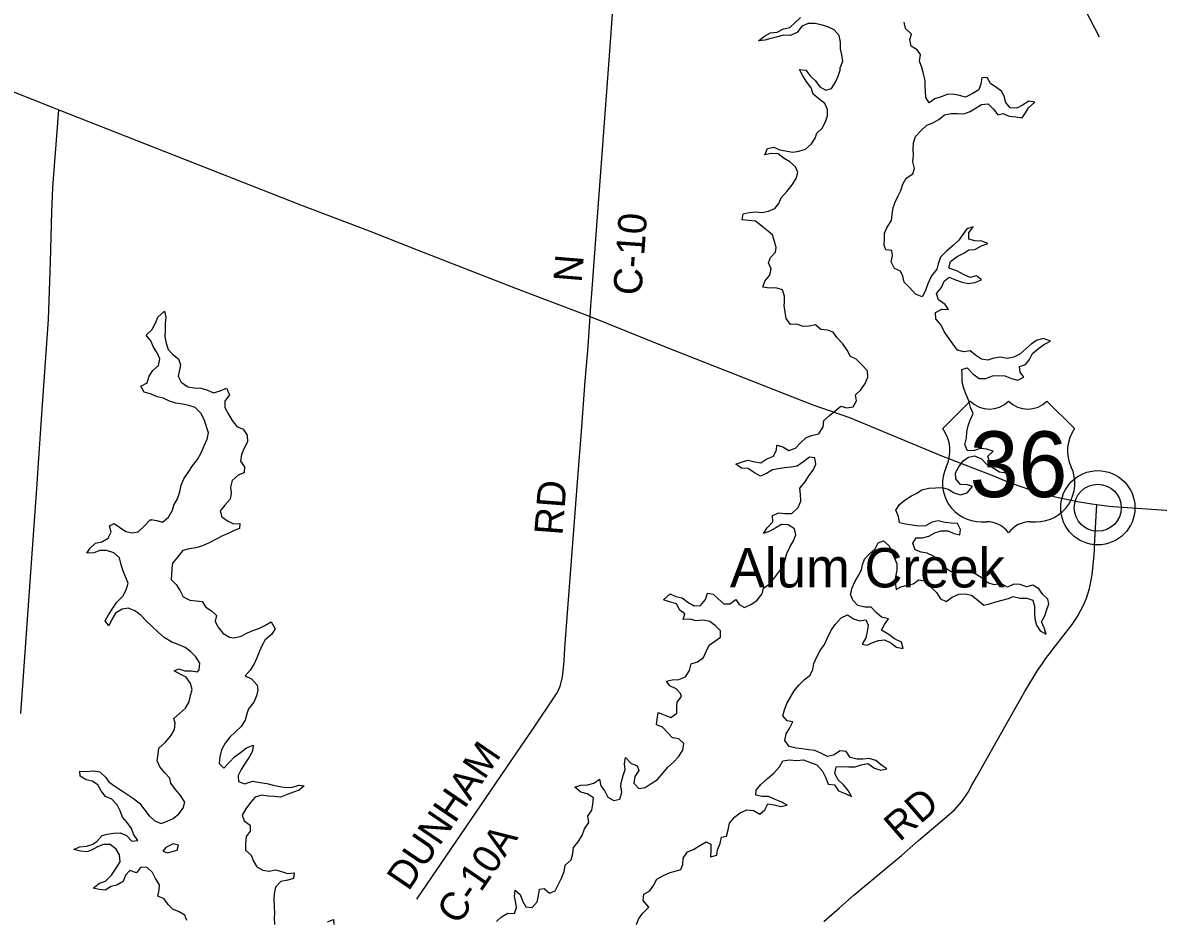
# Model space of a CAD drawing. Extents: x 1674899 to 2057726, y 653888 to 988278.
# Drawn here: x 1833082 to 1845104, y 821739 to 831243 of the extents above; entities that cross this region are included whole.
import ezdxf

# ---------------------------------------------------------------- set-up
doc = ezdxf.new("R2010")
doc.units = 0
for name, color, linetype in [('GM_X_County_Road', 7, 'Continuous'), ('GM_X_County_Road_Text', 7, 'Continuous'), ('GM_X_Major_Lake', 7, 'Continuous'), ('GM_X_Township_ROW', 7, 'Continuous'), ('GM_X_Unincorporated', 7, 'Continuous'), ('GM_X_Unincorporated_Location', 7, 'Continuous'), ('GM_X_Unincorporated_Text', 7, 'Continuous'), ('GM_X_US_Location', 7, 'Continuous'), ('GM_X_US_Route', 7, 'Continuous'), ('GM_X_US_Shield', 7, 'Continuous'), ('SH_Data', 7, 'Continuous')]:
    doc.layers.add(name, color=color, linetype=linetype)

msp = doc.modelspace()

# ---------------------------------------------------------------- linework, layer by layer
at = {"layer": 'GM_X_County_Road'}
for points in [[(1839090, 828131), (1839096, 828247), (1839106, 828377), (1839155, 829045), (1839297, 830940), (1839419, 832616), (1839427, 832761), (1839419, 832807), (1839405, 832831)], [(1833063, 823927), (1833158, 825274), (1833233, 826364), (1833244, 826526), (1833284, 827097), (1833354, 828099), (1833377, 828710), (1833389, 829242), (1833401, 829499), (1833463, 830322)], [(1837255, 821964), (1838352, 823573), (1838477, 823753), (1838734, 824138), (1838754, 824176), (1838776, 824230), (1838797, 824315), (1838813, 824478), (1838822, 824624), (1838961, 826468), (1838996, 826913), (1839038, 827452), (1839065, 827768), (1839090, 828131)], [(1844428, 825666), (1844430, 825701), (1844439, 825894), (1844455, 826141)], [(1843676, 824135), (1843691, 824163), (1843825, 824382), (1843877, 824459), (1843910, 824506), (1843948, 824557), (1844017, 824645), (1844192, 824870), (1844248, 824955), (1844313, 825075), (1844345, 825149), (1844376, 825251), (1844395, 825340), (1844404, 825395), (1844424, 825605), (1844428, 825666)], [(1841562, 821727), (1841728, 821872), (1841885, 822009), (1842387, 822426), (1842567, 822583), (1842842, 822816), (1842945, 822908), (1843026, 822996), (1843091, 823097), (1843134, 823175), (1843183, 823260), (1843512, 823845), (1843676, 824135)]]:
    msp.add_lwpolyline(points, dxfattribs=at)
at = {"layer": 'GM_X_Major_Lake'}
for points in [[(1841736, 830742), (1841738, 830766), (1841763, 830836), (1841755, 830904), (1841739, 830968), (1841739, 831036), (1841725, 831109), (1841674, 831169), (1841604, 831199), (1841536, 831219), (1841468, 831234), (1841396, 831236), (1841332, 831206), (1841280, 831140), (1841208, 831106), (1841138, 831111), (1841072, 831095), (1841002, 831077), (1840938, 831057), (1840872, 831052), (1840936, 831099), (1840998, 831135), (1841070, 831143), (1841136, 831179), (1841204, 831192), (1841258, 831240), (1841316, 831298)], [(1842619, 830703), (1842600, 830769), (1842576, 830837), (1842586, 830907), (1842552, 830957), (1842488, 830996), (1842475, 831066), (1842491, 831120), (1842429, 831182), (1842415, 831250)], [(1841142, 828250), (1841146, 828280), (1841148, 828348), (1841125, 828415), (1841055, 828437), (1840989, 828433), (1840917, 828443), (1840937, 828507), (1840993, 828571), (1841005, 828637), (1840976, 828701), (1840998, 828757), (1841050, 828813), (1841058, 828863), (1841042, 828927), (1841021, 828997), (1840961, 829048), (1840907, 829090), (1840839, 829140), (1840767, 829150), (1840700, 829155), (1840710, 829219), (1840774, 829232), (1840840, 829240), (1840908, 829234), (1840976, 829248), (1841044, 829276), (1841088, 829327), (1841112, 829389), (1841170, 829455), (1841228, 829527), (1841271, 829593), (1841287, 829657), (1841263, 829717), (1841205, 829769), (1841145, 829804), (1841080, 829854), (1841006, 829858), (1840940, 829844), (1840966, 829912), (1841034, 829926), (1841098, 829898), (1841234, 829873), (1841300, 829883), (1841368, 829905), (1841432, 829959), (1841472, 830021), (1841490, 830075), (1841544, 830126), (1841580, 830194), (1841603, 830258), (1841601, 830324), (1841575, 830386), (1841509, 830437), (1841452, 830487), (1841430, 830555), (1841382, 830615), (1841342, 830682), (1841305, 830748), (1841372, 830739), (1841418, 830679), (1841476, 830629), (1841522, 830565), (1841584, 830527), (1841646, 830546), (1841686, 830612), (1841714, 830678), (1841736, 830742)], [(1842898, 828642), (1842886, 828650), (1842904, 828714), (1842976, 828766), (1843044, 828802), (1843100, 828838), (1843162, 828843), (1843231, 828879), (1843299, 828905), (1843235, 828929), (1843163, 828935), (1843099, 828950), (1843097, 829018), (1843143, 829082), (1843079, 829062), (1843035, 829000), (1842991, 828940), (1842931, 828884), (1842861, 828825), (1842800, 828761), (1842774, 828691), (1842760, 828635), (1842704, 828563), (1842666, 828477), (1842639, 828409), (1842605, 828341), (1842533, 828369), (1842474, 828434), (1842414, 828496), (1842400, 828560), (1842374, 828612), (1842310, 828642), (1842275, 828711), (1842291, 828775), (1842285, 828831), (1842221, 828837), (1842201, 828887), (1842206, 828955), (1842206, 829015), (1842234, 829077), (1842278, 829147), (1842288, 829211), (1842299, 829285), (1842319, 829343), (1842351, 829409), (1842377, 829465), (1842401, 829533), (1842436, 829597), (1842506, 829644), (1842522, 829700), (1842506, 829771), (1842514, 829839), (1842509, 829907), (1842511, 829971), (1842535, 830039), (1842595, 830103), (1842655, 830158), (1842719, 830184), (1842780, 830218), (1842842, 830268), (1842910, 830282), (1842980, 830281), (1843046, 830279), (1843114, 830303), (1843234, 830378), (1843302, 830384), (1843361, 830328), (1843405, 830268), (1843461, 830281), (1843525, 830253), (1843595, 830247), (1843663, 830237), (1843697, 830289), (1843729, 830341), (1843797, 830402), (1843735, 830411), (1843665, 830369), (1843605, 830337), (1843535, 830343), (1843490, 830399), (1843474, 830464), (1843444, 830518), (1843386, 830560), (1843328, 830600), (1843293, 830662), (1843235, 830661), (1843227, 830595), (1843204, 830533), (1843134, 830491), (1843064, 830455), (1842998, 830471), (1842930, 830486), (1842870, 830482), (1842806, 830458), (1842740, 830438), (1842678, 830396), (1842642, 830451), (1842641, 830519), (1842637, 830571), (1842635, 830631), (1842619, 830703)], [(1843042, 828576), (1842970, 828616), (1842898, 828642)], [(1842490, 826232), (1842540, 826258), (1842602, 826297), (1842674, 826313), (1842746, 826319), (1842812, 826321), (1842880, 826304), (1842942, 826264), (1843011, 826244), (1843081, 826264), (1843138, 826333), (1843084, 826348), (1843010, 826352), (1842962, 826414), (1842958, 826478), (1842992, 826542), (1843039, 826604), (1843095, 826642), (1843159, 826656), (1843231, 826625), (1843286, 826569), (1843356, 826531), (1843424, 826487), (1843496, 826476), (1843442, 826541), (1843382, 826571), (1843318, 826593), (1843299, 826653), (1843357, 826705), (1843289, 826729), (1843217, 826736), (1843157, 826712), (1843085, 826708), (1843057, 826776), (1843073, 826846), (1843078, 826910), (1843092, 826974), (1843114, 827036), (1843144, 827106), (1843115, 827168), (1843097, 827240), (1843069, 827305), (1843045, 827371), (1843028, 827437), (1843028, 827507), (1843024, 827571), (1843082, 827587), (1843142, 827524), (1843208, 827476), (1843280, 827476), (1843348, 827504), (1843414, 827509), (1843481, 827503), (1843549, 827477), (1843617, 827457), (1843681, 827490), (1843641, 827543), (1843636, 827603), (1843700, 827624), (1843740, 827678), (1843774, 827742), (1843836, 827794), (1843900, 827838), (1843962, 827872), (1843890, 827898), (1843822, 827880), (1843762, 827842), (1843702, 827789), (1843640, 827735), (1843574, 827703), (1843506, 827687), (1843434, 827702), (1843362, 827692), (1843300, 827670), (1843232, 827682), (1843168, 827724), (1843113, 827767), (1843045, 827759), (1842979, 827775), (1842929, 827841), (1842883, 827906), (1842838, 827972), (1842804, 828040), (1842750, 828108), (1842744, 828176), (1842812, 828210), (1842882, 828206), (1842849, 828258), (1842777, 828308), (1842757, 828377), (1842809, 828438), (1842836, 828506), (1842892, 828550), (1842959, 828520), (1843027, 828496), (1843091, 828481), (1843163, 828493), (1843233, 828521), (1843179, 828561), (1843113, 828545), (1843042, 828576)], [(1841265, 826739), (1841315, 826795), (1841377, 826852), (1841447, 826874), (1841511, 826890), (1841557, 826964), (1841565, 827030), (1841622, 827084), (1841680, 827129), (1841744, 827183), (1841808, 827165), (1841874, 827177), (1841910, 827239), (1841900, 827303), (1841954, 827355), (1842000, 827423), (1842029, 827488), (1842025, 827557), (1841967, 827619), (1841905, 827679), (1841844, 827709), (1841812, 827774), (1841764, 827842), (1841704, 827906), (1841663, 827966), (1841603, 827988), (1841533, 827995), (1841475, 828043), (1841409, 828031), (1841345, 828025), (1841277, 828050), (1841209, 828048), (1841163, 828110), (1841154, 828178), (1841142, 828250)], [(1834444, 825977), (1834438, 825983), (1834500, 825971), (1834563, 825954), (1834626, 826008), (1834668, 826082), (1834682, 826134), (1834720, 826202), (1834744, 826276), (1834759, 826346), (1834787, 826414), (1834833, 826480), (1834881, 826550), (1834931, 826618), (1834970, 826689), (1835004, 826763), (1835034, 826833), (1835050, 826901), (1835003, 827042), (1834969, 827108), (1834909, 827168), (1834841, 827188), (1834772, 827205), (1834702, 827213), (1834634, 827235), (1834572, 827269), (1834504, 827282), (1834434, 827312), (1834366, 827330), (1834333, 827394), (1834399, 827428), (1834421, 827500), (1834461, 827560), (1834521, 827614), (1834533, 827684), (1834504, 827746), (1834468, 827808), (1834438, 827876), (1834388, 827936), (1834449, 827990), (1834487, 828060), (1834513, 828126), (1834583, 828188), (1834597, 828124), (1834591, 828056), (1834589, 827990), (1834588, 827918), (1834600, 827850), (1834620, 827782), (1834670, 827731), (1834731, 827683), (1834753, 827621), (1834737, 827551), (1834729, 827501), (1834758, 827437), (1834830, 827388), (1834898, 827376), (1834966, 827374), (1835032, 827354), (1835102, 827323), (1835172, 827345), (1835240, 827373), (1835270, 827303), (1835221, 827235), (1835221, 827167), (1835261, 827097), (1835299, 827031), (1835348, 826966), (1835414, 826938), (1835458, 826876), (1835460, 826806), (1835425, 826738), (1835397, 826670), (1835387, 826602), (1835429, 826540), (1835425, 826476), (1835364, 826452), (1835298, 826394), (1835280, 826326), (1835290, 826262), (1835278, 826198), (1835223, 826134), (1835173, 826076), (1835189, 826010), (1835251, 825970), (1835313, 825938), (1835381, 825941), (1835376, 825887), (1835322, 825866), (1835250, 825830), (1835198, 825808), (1835130, 825776), (1835054, 825734), (1834986, 825703), (1834916, 825683), (1834844, 825671), (1834776, 825653), (1834720, 825585), (1834668, 825522), (1834662, 825468), (1834657, 825398)], [(1840056, 824109), (1840046, 824141), (1840001, 824191), (1839933, 824222), (1839899, 824272), (1839957, 824286), (1840029, 824287), (1840099, 824317), (1840141, 824385), (1840159, 824455), (1840225, 824477), (1840288, 824521), (1840318, 824586), (1840350, 824652), (1840410, 824694), (1840468, 824738), (1840468, 824804), (1840415, 824856), (1840355, 824903), (1840283, 824915), (1840213, 824909), (1840143, 824927), (1840075, 824922), (1840093, 824984), (1840040, 825024), (1840002, 825090), (1839930, 825110), (1839866, 825131), (1839936, 825196), (1839998, 825168), (1840062, 825154), (1840124, 825106), (1840190, 825069), (1840258, 825073), (1840312, 825137), (1840332, 825203), (1840392, 825193), (1840444, 825142), (1840503, 825090), (1840569, 825090), (1840633, 825136), (1840667, 825084), (1840725, 825051), (1840797, 825085), (1840859, 825129), (1840911, 825195), (1840926, 825255), (1840984, 825297), (1841032, 825352), (1841084, 825422), (1841136, 825490), (1841154, 825554), (1841173, 825624), (1841203, 825690), (1841243, 825756), (1841267, 825820), (1841252, 825884), (1841186, 825926), (1841116, 825929), (1841056, 825893), (1840992, 825859), (1840926, 825835), (1840964, 825895), (1841022, 825959), (1841020, 826025), (1841086, 826053), (1841152, 826045), (1841224, 826046), (1841292, 826108), (1841321, 826178), (1841317, 826246), (1841311, 826316), (1841367, 826382), (1841405, 826444), (1841452, 826506), (1841478, 826570), (1841468, 826634), (1841412, 826644), (1841352, 826598), (1841280, 826546), (1841216, 826537), (1841148, 826531), (1841080, 826519), (1841020, 826509), (1840958, 826468), (1840894, 826442), (1840830, 826478), (1840764, 826522), (1840692, 826525), (1840633, 826569), (1840699, 826595), (1840763, 826610), (1840834, 826592), (1840898, 826584), (1840960, 826626), (1841032, 826653), (1841063, 826719), (1841065, 826769), (1841131, 826753), (1841193, 826713), (1841265, 826739)], [(1841858, 825227), (1841859, 825251), (1841893, 825321), (1841929, 825389), (1841961, 825451), (1841972, 825501), (1841994, 825563), (1842046, 825619), (1842106, 825673), (1842138, 825737), (1842194, 825756), (1842254, 825704), (1842278, 825640), (1842310, 825572), (1842337, 825512), (1842335, 825446), (1842321, 825376), (1842317, 825314), (1842328, 825242), (1842378, 825269), (1842444, 825287), (1842508, 825301), (1842569, 825345), (1842634, 825333), (1842696, 825268), (1842756, 825208), (1842798, 825142), (1842860, 825114), (1842922, 825159), (1842992, 825191), (1843060, 825197), (1843126, 825183), (1843193, 825130), (1843257, 825074), (1843319, 825090), (1843385, 825110), (1843453, 825129), (1843519, 825147), (1843569, 825167), (1843641, 825149), (1843713, 825150), (1843777, 825128), (1843793, 825064), (1843794, 824998), (1843796, 824930), (1843816, 824864), (1843854, 824802), (1843919, 824767), (1843896, 824836), (1843868, 824900), (1843902, 824962), (1843926, 825028), (1843946, 825088), (1843935, 825140), (1843881, 825190), (1843841, 825250), (1843777, 825286), (1843709, 825269), (1843641, 825295), (1843576, 825299), (1843507, 825267), (1843438, 825304), (1843368, 825290), (1843300, 825312), (1843230, 825368), (1843166, 825407), (1843094, 825429), (1843022, 825419), (1842955, 825419), (1842903, 825432), (1842841, 825476), (1842783, 825538), (1842723, 825596), (1842657, 825625), (1842594, 825635), (1842530, 825663), (1842504, 825731), (1842540, 825787), (1842608, 825789), (1842674, 825805), (1842738, 825841), (1842806, 825864), (1842876, 825864), (1842942, 825836), (1843004, 825820), (1843012, 825878), (1842980, 825942), (1842912, 825944), (1842844, 825952), (1842775, 825969), (1842711, 825953), (1842641, 825917), (1842569, 825913), (1842499, 825922), (1842429, 825932), (1842365, 825948), (1842355, 826016), (1842325, 826080), (1842364, 826140), (1842426, 826190), (1842490, 826232)], [(1834932, 824370), (1834950, 824390), (1834956, 824462), (1834916, 824528), (1834862, 824580), (1834803, 824626), (1834727, 824659), (1834661, 824685), (1834581, 824733), (1834521, 824786), (1834454, 824850), (1834388, 824908), (1834332, 824970), (1834268, 825017), (1834203, 825045), (1834133, 825033), (1834064, 824991), (1834026, 824925), (1833992, 824855), (1833956, 824908), (1833990, 824972), (1834035, 825043), (1834077, 825107), (1834141, 825171), (1834177, 825239), (1834199, 825307), (1834170, 825375), (1834148, 825427), (1834124, 825502), (1834108, 825578), (1834045, 825630), (1833969, 825654), (1833899, 825654), (1833833, 825629), (1833761, 825627), (1833797, 825679), (1833853, 825731), (1833919, 825746), (1833987, 825784), (1834018, 825850), (1834000, 825914), (1834050, 825942), (1834106, 825900), (1834173, 825856), (1834241, 825841), (1834305, 825853), (1834367, 825913), (1834430, 825979), (1834444, 825977)], [(1834657, 825398), (1834655, 825346), (1834707, 825293), (1834749, 825229), (1834782, 825163), (1834850, 825127), (1834918, 825122), (1834980, 825116), (1835020, 825054), (1835082, 825016), (1835133, 824966), (1835119, 824906), (1835149, 824845), (1835201, 824779), (1835271, 824737), (1835322, 824729), (1835394, 824746), (1835463, 824784), (1835517, 824808), (1835583, 824830), (1835645, 824860), (1835711, 824899), (1835756, 824825), (1835718, 824767), (1835650, 824707), (1835618, 824652), (1835588, 824588), (1835562, 824518), (1835529, 824446), (1835489, 824388), (1835437, 824326), (1835505, 824294), (1835564, 824227), (1835570, 824177), (1835556, 824115), (1835530, 824047), (1835472, 823978), (1835456, 823926), (1835437, 823858), (1835395, 823792), (1835333, 823734), (1835273, 823678), (1835225, 823614), (1835186, 823542), (1835168, 823470), (1835160, 823398), (1835212, 823350), (1835270, 823414), (1835324, 823470), (1835386, 823516), (1835450, 823565), (1835520, 823593), (1835514, 823531), (1835478, 823465), (1835438, 823401), (1835394, 823337), (1835363, 823273), (1835367, 823207), (1835433, 823183), (1835483, 823201), (1835523, 823213)], [(1841676, 823174), (1841717, 823110), (1841789, 823080), (1841855, 823048), (1841821, 823114), (1841770, 823172), (1841714, 823226), (1841680, 823294), (1841694, 823362), (1841764, 823368), (1841826, 823362), (1841896, 823364), (1841960, 823386), (1842030, 823399), (1842100, 823351), (1842166, 823327), (1842230, 823342), (1842176, 823377), (1842114, 823431), (1842042, 823451), (1841976, 823445), (1841912, 823446), (1841842, 823464), (1841801, 823526), (1841735, 823532), (1841665, 823487), (1841603, 823473), (1841533, 823509), (1841469, 823537), (1841401, 823544), (1841333, 823554), (1841269, 823560), (1841197, 823578), (1841150, 823643), (1841164, 823713), (1841202, 823775), (1841236, 823841), (1841174, 823851), (1841131, 823903), (1841147, 823967), (1841171, 824035), (1841209, 824101), (1841249, 824167), (1841298, 824229), (1841358, 824288), (1841420, 824336), (1841448, 824396), (1841456, 824458), (1841487, 824522), (1841523, 824594), (1841571, 824660), (1841603, 824730), (1841637, 824802), (1841684, 824872), (1841746, 824940), (1841814, 824973), (1841878, 824931), (1841940, 824911), (1842008, 824921), (1842033, 824862), (1842023, 824798), (1842007, 824730), (1841969, 824662), (1842023, 824652), (1842073, 824678), (1842143, 824702), (1842207, 824710), (1842274, 824675), (1842334, 824631), (1842404, 824617), (1842386, 824683), (1842313, 824719), (1842251, 824764), (1842175, 824812), (1842205, 824872), (1842249, 824932), (1842175, 824950), (1842122, 824996), (1842066, 825056), (1841998, 825053), (1841924, 825071), (1841870, 825127), (1841847, 825189), (1841858, 825227)], [(1834327, 822296), (1834285, 822243), (1834215, 822267), (1834171, 822215), (1834144, 822149), (1834078, 822111), (1834018, 822095), (1833954, 822056), (1833892, 822066), (1833828, 822080), (1833893, 822132), (1833957, 822152), (1834023, 822215), (1834071, 822289), (1834113, 822359), (1834107, 822433), (1834072, 822493), (1834006, 822542), (1833938, 822542), (1833874, 822518), (1833810, 822480), (1833760, 822465), (1833692, 822469), (1833624, 822487), (1833684, 822515), (1833756, 822523), (1833816, 822542), (1833866, 822572), (1833924, 822636), (1833976, 822652), (1834044, 822660), (1834112, 822665), (1834182, 822635), (1834238, 822577), (1834300, 822583), (1834254, 822651), (1834234, 822711), (1834187, 822775), (1834139, 822831), (1834113, 822896), (1834081, 822960), (1834026, 823022), (1833958, 823050), (1833914, 823110), (1833876, 823173), (1833818, 823213), (1833755, 823225), (1833691, 823265), (1833685, 823317), (1833753, 823315), (1833829, 823321), (1833897, 823309), (1833958, 823256), (1833994, 823204), (1834056, 823158), (1834126, 823114), (1834190, 823069), (1834253, 823029), (1834317, 822979), (1834365, 822919), (1834419, 822846), (1834480, 822792), (1834548, 822762), (1834612, 822790), (1834676, 822816), (1834734, 822865), (1834779, 822925), (1834797, 822991), (1834753, 823059), (1834701, 823124), (1834650, 823190), (1834640, 823242), (1834586, 823300), (1834532, 823362), (1834505, 823427), (1834515, 823497), (1834523, 823563), (1834593, 823626), (1834651, 823692), (1834688, 823758), (1834696, 823826), (1834682, 823876), (1834742, 823930), (1834806, 823986), (1834844, 824052), (1834859, 824120), (1834875, 824184), (1834857, 824246), (1834811, 824314), (1834750, 824346), (1834684, 824381), (1834734, 824401), (1834798, 824380), (1834864, 824380), (1834932, 824370)], [(1838097, 821726), (1838152, 821776), (1838218, 821814), (1838290, 821810), (1838310, 821874), (1838300, 821940), (1838290, 821990), (1838296, 822056), (1838348, 822012), (1838372, 821944), (1838410, 821881), (1838476, 821875), (1838528, 821933), (1838544, 821999), (1838552, 822069), (1838604, 822077), (1838660, 822027), (1838720, 822050), (1838754, 822120), (1838785, 822184), (1838815, 822254), (1838825, 822324), (1838887, 822380), (1838905, 822446), (1838914, 822510), (1838964, 822568), (1839004, 822638), (1839030, 822706), (1839074, 822774), (1839065, 822842), (1839107, 822906), (1839119, 822970), (1839125, 823036), (1839057, 823078), (1838990, 823096), (1838928, 823148), (1838992, 823168), (1839062, 823172), (1839128, 823192), (1839188, 823234), (1839204, 823161), (1839245, 823105), (1839275, 823041), (1839339, 823007), (1839405, 823023), (1839423, 823091), (1839415, 823159), (1839420, 823209), (1839438, 823271), (1839460, 823337), (1839452, 823397), (1839462, 823461), (1839520, 823402), (1839588, 823374), (1839604, 823324), (1839564, 823260), (1839553, 823190), (1839605, 823134), (1839673, 823144), (1839735, 823188), (1839803, 823231), (1839862, 823301), (1839910, 823361), (1839972, 823413), (1840026, 823471), (1840070, 823539), (1840082, 823609), (1840029, 823661), (1839961, 823669), (1839911, 823723), (1839857, 823782), (1839791, 823808), (1839798, 823868), (1839810, 823938), (1839874, 823914), (1839942, 823887), (1840006, 823933), (1840006, 823997), (1840010, 824049), (1840056, 824109)], [(1839580, 821695), (1839606, 821757), (1839652, 821819), (1839711, 821879), (1839649, 821947), (1839659, 822015), (1839721, 822049), (1839761, 822107), (1839794, 822175), (1839866, 822212), (1839938, 822244), (1839988, 822260), (1840050, 822276), (1840072, 822330), (1840074, 822398), (1840120, 822462), (1840184, 822489), (1840251, 822529), (1840317, 822569), (1840368, 822545), (1840366, 822477), (1840362, 822409), (1840432, 822430), (1840438, 822486), (1840466, 822552), (1840479, 822618), (1840533, 822628), (1840549, 822696), (1840563, 822768), (1840617, 822832), (1840679, 822878), (1840747, 822910), (1840819, 822901), (1840885, 822861), (1840937, 822907), (1840969, 822971), (1841037, 822963), (1841107, 822942), (1841175, 822956), (1841117, 822990), (1841048, 823019), (1840976, 823051), (1840910, 823051), (1840844, 823065), (1840848, 823115), (1840898, 823177), (1840966, 823239), (1841033, 823297), (1841095, 823363), (1841131, 823427), (1841201, 823438), (1841275, 823432), (1841347, 823438), (1841423, 823411), (1841489, 823385), (1841550, 823319), (1841586, 823247), (1841608, 823179), (1841676, 823174)], [(1835523, 823213), (1835533, 823209), (1835597, 823197), (1835667, 823186), (1835733, 823170), (1835804, 823154), (1835868, 823146), (1835938, 823147), (1836006, 823169), (1836062, 823161), (1836008, 823117), (1835948, 823097), (1835882, 823069), (1835812, 823042), (1835746, 823048), (1835680, 823054), (1835612, 823062), (1835544, 823043), (1835494, 822985), (1835444, 822919), (1835404, 822851), (1835426, 822793), (1835489, 822745), (1835489, 822683), (1835447, 822625), (1835441, 822553), (1835442, 822483), (1835500, 822428), (1835524, 822364), (1835562, 822304), (1835624, 822270), (1835691, 822260), (1835757, 822273), (1835823, 822257), (1835885, 822233), (1835957, 822243), (1835947, 822183), (1835887, 822165), (1835815, 822151), (1835757, 822091), (1835743, 822019), (1835742, 821965), (1835744, 821879), (1835746, 821815), (1835744, 821763), (1835747, 821695)], [(1834730, 822534), (1834674, 822547), (1834598, 822510), (1834566, 822472)], [(1834566, 822472), (1834616, 822453), (1834718, 822480), (1834730, 822534)], [(1834818, 821736), (1834799, 821792), (1834731, 821833), (1834669, 821855), (1834623, 821905), (1834581, 821965), (1834514, 821994), (1834526, 822062), (1834530, 822114), (1834486, 822182), (1834456, 822246), (1834395, 822300), (1834327, 822296)], [(1836309, 821723), (1836373, 821747), (1836377, 821695)]]:
    msp.add_lwpolyline(points, dxfattribs=at)
at = {"layer": 'GM_X_Township_ROW'}
msp.add_lwpolyline([(1843586, 832773), (1843609, 832772), (1844480, 831093)], dxfattribs=at)
at = {"layer": 'GM_X_Unincorporated'}
for radius in [393, 249]:
    msp.add_circle((1844464, 826107), radius, dxfattribs=at)
at = {"layer": 'GM_X_Unincorporated_Location'}
msp.add_line((1844464, 826107), (1844464, 826107), dxfattribs=at)
at = {"layer": 'GM_X_US_Route'}
for points in [[(1831379, 831146), (1833393, 830350), (1833463, 830322), (1836024, 829315), (1836751, 829041), (1837258, 828837), (1838300, 828432), (1839090, 828131), (1839877, 827816), (1841448, 827196), (1841834, 827061), (1842819, 826655), (1843343, 826451), (1843520, 826379), (1843742, 826300), (1843999, 826225), (1844265, 826170), (1844402, 826149)], [(1844402, 826149), (1844455, 826141), (1844585, 826124), (1844623, 826121), (1846005, 826026), (1846509, 825988)]]:
    msp.add_lwpolyline(points, dxfattribs=at)
at = {"layer": 'GM_X_US_Shield'}
for p, q in [((1843114, 827235), (1842824, 826945)), ((1844216, 826945), (1843926, 827235)), ((1843230, 825959), (1843288, 825959)), ((1843752, 825959), (1843810, 825959))]:
    msp.add_line(p, q, dxfattribs=at)
for centre, radius, start, end in [((1843317, 827442), 290, 225.573, 314.427), ((1843723, 827442), 290, 225.573, 314.427), ((1842492, 826712), 406, 334.5471, 35.0009), ((1844549, 826712), 406, 144.9991, 205.4529), ((1843226, 826365), 406, 154.8319, 270.6383), ((1843815, 826365), 406, 269.3617, 25.1681), ((1843288, 825669), 290, 36.8699, 90), ((1843752, 825669), 290, 90, 143.1301)]:
    msp.add_arc(centre, radius, start, end, dxfattribs=at)
at = {"layer": 'SH_Data'}
for points in [[(1831379, 831146), (1833393, 830350), (1833463, 830322), (1836024, 829315), (1836751, 829041), (1837258, 828837), (1838300, 828432), (1839090, 828131), (1839877, 827816), (1841448, 827196), (1841834, 827061), (1842819, 826655), (1843343, 826451), (1843520, 826379), (1843742, 826300), (1843999, 826225), (1844265, 826170), (1844402, 826149)], [(1844402, 826149), (1844455, 826141), (1844585, 826124), (1844623, 826121), (1846005, 826026), (1846509, 825988)]]:
    msp.add_lwpolyline(points, dxfattribs=at)

# ---------------------------------------------------------------- texts
at = {"layer": 'GM_X_County_Road_Text'}
for s, rotation, p in [('C-10', 85.8896, (1839631, 828350)), ('N', 85.2351, (1838998, 828485)), ('RD', 85.5641, (1838796, 825809)), ('DUNHAM', 55.7593, (1837166, 822038)), ('RD', 40.8148, (1842365, 822563)), ('C-10A', 55.7513, (1837694, 821678))]:
    msp.add_text(s, height=300, rotation=rotation, dxfattribs=at).set_placement(p)
at = {"layer": 'GM_X_Unincorporated_Text'}
msp.add_text('Alum Creek', height=417, rotation=0, dxfattribs=at).set_placement((1840568, 825263))
at = {"layer": 'GM_X_US_Location'}
for s in ['0', '/']:
    msp.add_text(s, height=1, dxfattribs=at).set_placement((1843520, 826563))
msp.add_text('36', height=1, rotation=0, dxfattribs=at).set_placement((1843314, 826356))
at = {"layer": 'GM_X_US_Shield'}
msp.add_text('36', height=696.1, dxfattribs=at).set_placement((1843107, 826220))

doc.saveas('drawing.dxf')
